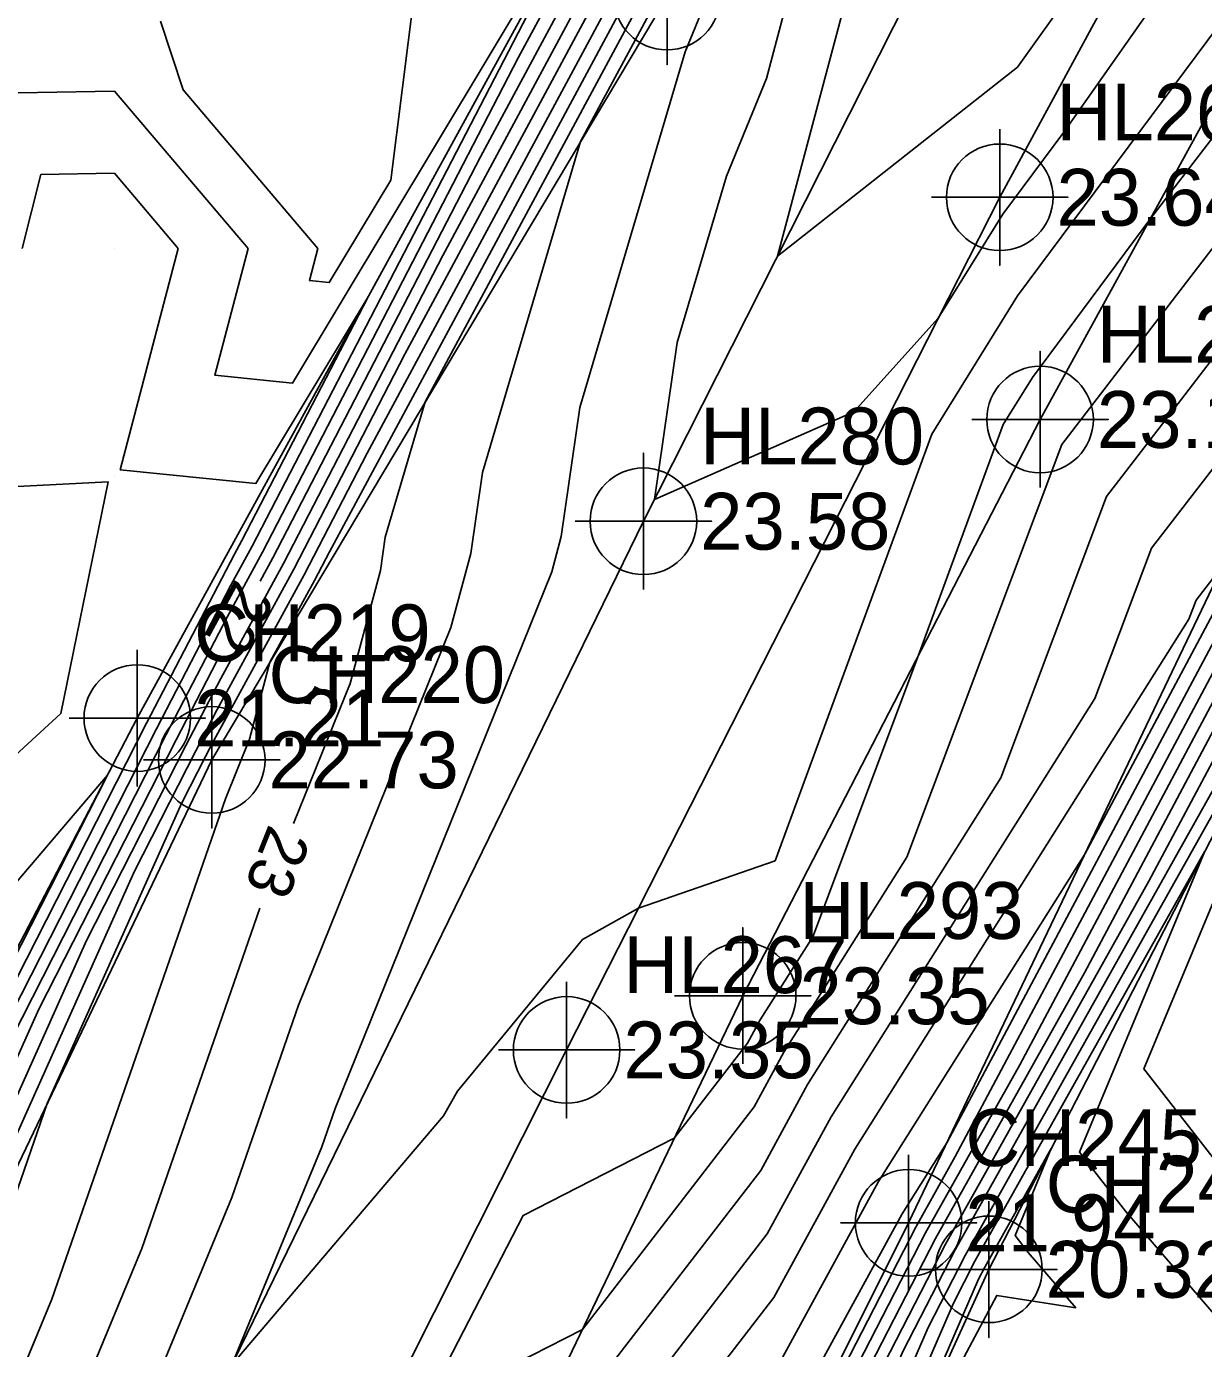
# Model space of a CAD drawing. Extents: x 2531902 to 2533249, y 715219 to 716099.
# Drawn here: x 2532916.1 to 2532967.9, y 715771.6 to 715829.8 of the extents above; entities that cross this region are included whole.
import ezdxf

# ---------------------------------------------------------------- set-up
doc = ezdxf.new("R2010")
doc.units = 0
for name, color, linetype in [('DTM Contours Major', 7, 'Continuous'), ('DTM Contours Major Text', 7, 'Continuous'), ('DTM Contours Minor', 7, 'Continuous'), ('Exist DTM Breakline', 7, 'Continuous'), ('Exist DTM Breakline Cogo Elevation', 7, 'Continuous'), ('Exist DTM Breakline Cogo Number', 7, 'Continuous'), ('Exist DTM Breakline Cogo Point CELL', 7, 'Continuous'), ('Exist DTM Crownline', 7, 'Continuous'), ('Exist DTM Crownline Cogo Elevation', 7, 'Continuous'), ('Exist DTM Crownline Cogo Number', 7, 'Continuous'), ('Exist DTM Crownline Cogo Point CELL', 7, 'Continuous'), ('Exist DTM QL2 LIDAR Elevation Point', 7, 'Continuous'), ('Exist Roads Soil', 7, 'Continuous'), ('Exist Roads Soil Cogo Elevation', 7, 'Continuous'), ('Exist Roads Soil Cogo Number', 7, 'Continuous'), ('Exist Roads Soil Cogo Point CELL', 7, 'Continuous')]:
    doc.layers.add(name, color=color, linetype=linetype)

msp = doc.modelspace()

# ---------------------------------------------------------------- linework, layer by layer
at = {"layer": 'DTM Contours Major'}
for points in [[(2532974.311, 715893.136), (2532962.46, 715871.481), (2532962.278, 715871.136), (2532960.23, 715867.394), (2532948.234, 715846.192), (2532945.525, 715841.222), (2532941.981, 715834.931), (2532940.907, 715832.959), (2532936.106, 715824.028), (2532926.974, 715806.393), (2532926.413, 715805.363)], [(2532972.197, 715883.951), (2532970.304, 715880.392), (2532964.86, 715870.446), (2532963.229, 715867.364), (2532962.476, 715865.987), (2532958.062, 715858.186), (2532947.982, 715839.692), (2532947.015, 715837.976), (2532943.502, 715831.522), (2532933.674, 715813.243), (2532931.908, 715807.29), (2532931.698, 715805.829), (2532930.375, 715800.865), (2532927.885, 715794.695)], [(2532935.185, 715767.309), (2532936.846, 715770.53), (2532940.585, 715772.44), (2532948.143, 715782.24), (2532949.453, 715784.64), (2532954.859, 715793.213), (2532961.679, 715811.367), (2532962.756, 715812.763), (2532974.003, 715827.414), (2532982.304, 715840.432), (2532983.884, 715842.624), (2532986.227, 715846.362), (2532988.704, 715850.418)], [(2532940.427, 715752.913), (2532947.909, 715766.076), (2532949.587, 715768.252), (2532954.651, 715777.527), (2532956.624, 715780.657), (2532968.862, 715803.641), (2532970.137, 715805.875), (2532974.043, 715813.166), (2532980.171, 715824.204), (2532988.171, 715839.431), (2532988.73, 715840.42)], [(2532947.883, 715757.336), (2532952.088, 715765.474), (2532954.69, 715771.469), (2532956.99, 715775.945), (2532968.355, 715796.209), (2532971.516, 715802.146), (2532976.228, 715810.406), (2532976.683, 715811.256), (2532981.302, 715819.574), (2532979.344, 715814.39), (2532979.091, 715812.432), (2532984.65, 715813.744), (2532990.818, 715811.156), (2532984.286, 715810.253), (2532982.785, 715810.371), (2532981.484, 715810.238)], [(2532924.512, 715801.844), (2532922.712, 715798.378), (2532916.679, 715786.53), (2532909.832, 715771.258), (2532907.404, 715766.443), (2532903.158, 715756.872), (2532900.931, 715750.96), (2532890.629, 715729.59), (2532889.617, 715727.08), (2532883.368, 715714.157), (2532882.093, 715711.334)], [(2532926.402, 715790.98), (2532921.205, 715776.01), (2532917.456, 715766.943), (2532915.445, 715761.302), (2532907.4, 715743.928), (2532903.178, 715734.67), (2532899.089, 715725.845), (2532896.932, 715721.119), (2532887.609, 715704.047), (2532886.836, 715702.631), (2532884.884, 715700.293)]]:
    msp.add_lwpolyline(points, dxfattribs=at)
at = {"layer": 'DTM Contours Minor'}
for points in [[(2532978.605, 715897.015), (2532971.537, 715883.729), (2532964.38, 715870.653), (2532963.039, 715868.118), (2532962.027, 715866.268), (2532956.096, 715855.787), (2532947.491, 715839.998), (2532946.008, 715837.367), (2532942.983, 715831.81), (2532929.455, 715806.649), (2532928.803, 715805.39), (2532926.843, 715801.791), (2532925.943, 715798.415), (2532924.885, 715795.792), (2532917.242, 715773.777), (2532914.997, 715768.345), (2532911.892, 715759.638), (2532906.456, 715747.898), (2532899.692, 715733.067), (2532896.805, 715726.836), (2532893.28, 715719.109), (2532886.559, 715706.802)], [(2532979.486, 715896.632), (2532969.071, 715877.054), (2532965.34, 715870.238), (2532963.42, 715866.609), (2532962.925, 715865.706), (2532960.028, 715860.585), (2532948.473, 715839.387), (2532948.022, 715838.585), (2532944.021, 715831.235), (2532940.505, 715824.696), (2532936.189, 715810.144), (2532935.675, 715806.573), (2532934.806, 715803.315), (2532928.105, 715786.707), (2532925.167, 715778.244), (2532919.916, 715765.541), (2532918.998, 715762.966), (2532908.344, 715739.958), (2532906.663, 715736.273), (2532901.372, 715724.854), (2532900.585, 715723.128), (2532888.659, 715701.292)], [(2532980.806, 715896.056), (2532974.415, 715884.041), (2532975.418, 715873.531), (2532973.91, 715870.926), (2532973.877, 715870.057), (2532963.239, 715858.875), (2532955.103, 715841.953), (2532949.17, 715819.66), (2532959.725, 715827.976), (2532969.363, 715841.46), (2532973.494, 715847.335), (2532974.223, 715848.244), (2532975.261, 715849.693), (2532979.719, 715856.686), (2532991.661, 715874.393), (2532992.633, 715875.956), (2532996.105, 715881.12), (2533004.003, 715895.09)], [(2532923.186, 715712.886), (2532930.858, 715737.702), (2532931.519, 715738.867), (2532931.565, 715739.012), (2532935.901, 715749.684), (2532944.529, 715764.866), (2532949.298, 715771.05), (2532953.612, 715778.95), (2532962.696, 715793.355), (2532968.331, 715803.94), (2532968.918, 715804.969), (2532973.515, 715813.549), (2532977.321, 715820.404), (2532987.549, 715839.87), (2532988.835, 715842.147), (2532990.374, 715845.067), (2532998.16, 715859.118), (2533004.671, 715871.406), (2533006.64, 715874.927), (2533008.039, 715877.566), (2533018.511, 715895.173)], [(2532975.237, 715893.742), (2532962.94, 715871.274), (2532962.468, 715870.382), (2532960.68, 715867.113), (2532950.199, 715848.59), (2532946.016, 715840.916), (2532942.988, 715835.54), (2532941.426, 715832.672), (2532934.443, 715819.684), (2532927.431, 715806.142), (2532924.675, 715801.081), (2532923.145, 715798.135), (2532918.776, 715789.555), (2532910.427, 715770.931), (2532908.967, 715768.038), (2532903.853, 715756.506), (2532902.788, 715753.68), (2532891.061, 715729.356), (2532890.683, 715728.417), (2532883.705, 715713.988)], [(2532916.168, 715709.807), (2532922.937, 715719.046), (2532928.431, 715736.817), (2532929.391, 715738.509), (2532929.424, 715738.615), (2532935.705, 715754.076), (2532941.15, 715763.655), (2532949.009, 715773.848), (2532952.572, 715780.372), (2532967.273, 715803.685), (2532967.59, 715804.529), (2532968.767, 715806.054), (2532972.987, 715813.931), (2532974.472, 715816.605), (2532986.926, 715840.31), (2532987.791, 715841.84), (2532989.699, 715845.462), (2532995.142, 715855.284), (2533003.918, 715871.848), (2533005.351, 715874.411), (2533007.293, 715878.074), (2533014.98, 715890.997)], [(2532974.003, 715890.405), (2532963.42, 715871.067), (2532962.658, 715869.627), (2532961.129, 715866.831), (2532952.165, 715850.989), (2532946.508, 715840.61), (2532943.995, 715836.149), (2532941.945, 715832.384), (2532932.78, 715815.339), (2532927.888, 715805.891), (2532924.525, 715799.715), (2532923.578, 715797.892), (2532920.873, 715792.58), (2532911.022, 715770.605), (2532910.531, 715769.633), (2532905.461, 715758.203), (2532904.787, 715756.311), (2532904.568, 715755.838), (2532892.722, 715729.861), (2532892.238, 715728.818), (2532885.975, 715715.09)], [(2532972.77, 715887.067), (2532963.9, 715870.86), (2532962.849, 715868.873), (2532961.578, 715866.55), (2532954.131, 715853.388), (2532946.999, 715840.304), (2532945.001, 715836.758), (2532942.464, 715832.097), (2532931.118, 715810.994), (2532928.346, 715805.641), (2532924.375, 715798.35), (2532924.011, 715797.648), (2532922.97, 715795.605), (2532917.043, 715782.383), (2532913.28, 715771.543), (2532912.537, 715769.747), (2532908.34, 715757.975), (2532905.512, 715751.868), (2532896.207, 715731.464), (2532894.522, 715727.827), (2532889.628, 715717.099)], [(2532910.432, 715708.479), (2532922.688, 715725.206), (2532926.003, 715735.932), (2532927.262, 715738.151), (2532927.284, 715738.218), (2532935.51, 715758.468), (2532937.77, 715762.445), (2532948.721, 715776.645), (2532951.532, 715781.795), (2532963.135, 715800.194), (2532965.619, 715806.809), (2532971.138, 715813.959), (2532972.856, 715816.197), (2532975.967, 715821.075), (2532986.303, 715840.749), (2532986.747, 715841.534), (2532989.025, 715845.857), (2532992.123, 715851.449), (2533003.166, 715872.291), (2533004.063, 715873.895), (2533006.548, 715878.581), (2533011.449, 715886.821)], [(2532913.805, 715732.275), (2532924.716, 715749.822), (2532927.378, 715756.907), (2532927.487, 715757.103), (2532937.989, 715777.463), (2532944.628, 715780.854), (2532947.854, 715785.038), (2532948.414, 715786.062), (2532950.722, 715789.722), (2532955.375, 715802.111), (2532959.105, 715812.252), (2532960.387, 715814.323), (2532965.555, 715821.271), (2532974.576, 715833.023), (2532978.776, 715839.609), (2532982.024, 715844.114), (2532983.417, 715846.335), (2532990.678, 715858.227), (2532998.691, 715872.853), (2532999.363, 715873.971), (2533001.557, 715877.98), (2533006.576, 715886.786)], [(2532952.184, 715840.618), (2532948.685, 715827.47), (2532946.922, 715823.173), (2532944.752, 715815.853), (2532943.758, 715808.958), (2532952.525, 715812.81), (2532956.245, 715816.925), (2532959.082, 715821.509), (2532961.763, 715825.114), (2532974.339, 715842.999)], [(2532909.836, 715712.944), (2532918.233, 715725.627), (2532922.438, 715731.367), (2532923.576, 715735.047), (2532925.134, 715737.794), (2532925.143, 715737.821), (2532931.922, 715754.508), (2532934.359, 715760.993), (2532934.373, 715761.018), (2532935.703, 715763.597), (2532936.543, 715764.026), (2532948.432, 715779.443), (2532950.493, 715783.217), (2532958.997, 715796.704), (2532963.649, 715809.088), (2532966.947, 715813.361), (2532973.429, 715821.806), (2532985.17, 715840.216)], [(2532925.658, 715710.774), (2532927.519, 715718.451), (2532934.964, 715737.049), (2532935.713, 715739.472), (2532935.776, 715739.583), (2532935.847, 715739.806), (2532936.291, 715740.9), (2532940.806, 715748.843), (2532949.984, 715766.604), (2532950.251, 715767.219), (2532955.253, 715776.951), (2532956.992, 715780.051), (2532969.393, 715803.342), (2532971.355, 715806.781), (2532974.571, 715812.784), (2532983.021, 715828.003), (2532988.794, 715838.992)], [(2532913.207, 715826.793), (2532920, 715826.92), (2532925.88, 715820), (2532924.416, 715814.416), (2532927.837, 715814.075), (2532938.492, 715831.82), (2532938.664, 715833.186), (2532935.342, 715836.365), (2532939.783, 715834.071), (2532942.45, 715838.121), (2532939.967, 715833.714), (2532939.869, 715833.533), (2532939.431, 715832.718), (2532926.059, 715806.894), (2532925.125, 715805.179), (2532921.847, 715798.865), (2532912.485, 715780.48)], [(2532948.88, 715837.837), (2532945.112, 715828.649), (2532940.47, 715812.999), (2532939.652, 715807.318), (2532939.238, 715805.765), (2532929.715, 715782.164), (2532929.13, 715780.478), (2532925.165, 715770.887), (2532934.474, 715781.848), (2532935.093, 715782.92), (2532940.599, 715789.593), (2532943.059, 715790.969), (2532949.064, 715793.065), (2532955.964, 715811.824), (2532959.734, 715817.916), (2532974.936, 715838.353)], [(2532929.014, 715712.352), (2532931.932, 715724.385), (2532937.625, 715738.608), (2532937.738, 715738.951), (2532937.807, 715739.124), (2532940.835, 715746.3), (2532951.036, 715766.039), (2532952.47, 715769.344), (2532956.122, 715776.448), (2532962.674, 715788.13), (2532970.455, 715802.744), (2532973.791, 715808.593), (2532975.627, 715812.02), (2532988.72, 715835.602)], [(2532940.388, 715833.246), (2532937.768, 715828.373), (2532926.516, 715806.643), (2532924.975, 715803.813), (2532922.28, 715798.622), (2532914.582, 715783.505)], [(2532926.914, 715709.823), (2532929.726, 715721.418), (2532936.841, 715739.194), (2532936.891, 715739.346), (2532936.977, 715739.56), (2532938.296, 715742.685), (2532950.51, 715766.322), (2532951.361, 715768.281), (2532955.688, 715776.7), (2532959.833, 715784.091), (2532969.924, 715803.043), (2532972.573, 715807.687), (2532975.099, 715812.402), (2532985.871, 715831.803)], [(2532922.029, 715830), (2532923.029, 715826.971), (2532928.952, 715820), (2532928.58, 715818.58), (2532929.45, 715818.493), (2532932.16, 715823.006), (2532933.188, 715831.173)], [(2532915.941, 715820), (2532916.756, 715823.244), (2532920, 715823.304), (2532922.807, 715820), (2532920.253, 715810.253), (2532926.224, 715809.658), (2532931.156, 715817.871), (2532925.602, 715807.145), (2532925.275, 715806.544), (2532921.414, 715799.109), (2532910.388, 715777.455)], [(2532899.773, 715800.227), (2532897.398, 715810), (2532897.261, 715812.739), (2532900, 715819.554), (2532909.037, 715810), (2532910, 715809.229), (2532919.725, 715809.725), (2532917.647, 715799.54), (2532910, 715792.534), (2532901.322, 715798.678), (2532900, 715799.387), (2532899.042, 715799.042), (2532899.667, 715800), (2532899.773, 715800.227)], [(2532933.005, 715714.022), (2532931.949, 715718.326), (2532934.139, 715727.353), (2532938.409, 715738.022), (2532938.585, 715738.557), (2532938.637, 715738.688), (2532943.375, 715749.915), (2532951.562, 715765.757), (2532953.58, 715770.407), (2532956.556, 715776.197), (2532965.514, 715792.17), (2532970.985, 715802.445)], [(2532947.976, 715717.976), (2532942.283, 715720), (2532940.18, 715720.205), (2532940.055, 715721.165), (2532937.82, 715730.273), (2532938.551, 715733.287), (2532939.978, 715736.851), (2532940.278, 715737.768), (2532940.298, 715737.816), (2532948.455, 715757.144), (2532952.614, 715765.192), (2532955.799, 715772.532), (2532957.424, 715775.694), (2532971.196, 715800.249)], [(2532971.835, 715799.607), (2532965.29, 715783.909), (2532968.751, 715779.468)], [(2532909.055, 715784.335), (2532919.697, 715796.83), (2532908.291, 715774.43)], [(2532970.653, 715713.705), (2532960.031, 715720.008), (2532959.955, 715720.065), (2532950.186, 715722.11), (2532942.505, 715722.86), (2532940.762, 715736.22), (2532940.756, 715736.246), (2532940.758, 715736.255), (2532940.762, 715736.265), (2532941.125, 715737.373), (2532941.128, 715737.381), (2532950.995, 715760.759), (2532953.14, 715764.91), (2532956.909, 715773.595), (2532957.859, 715775.442), (2532967.974, 715793.478), (2532962.455, 715780.243), (2532964.478, 715777.648), (2532970, 715771.244)], [(2532962.299, 715773.399), (2532960.204, 715775.828), (2532959.62, 715776.577), (2532961.214, 715780.399), (2532958.293, 715775.191), (2532958.019, 715774.657), (2532953.666, 715764.627), (2532953.535, 715764.373), (2532952.789, 715762.606), (2532953.597, 715763.925), (2532954.78, 715762.105), (2532953.791, 715764.542), (2532953.981, 715764.849), (2532958.814, 715773.943), (2532962.299, 715773.399)]]:
    msp.add_lwpolyline(points, dxfattribs=at)
at = {"layer": 'Exist DTM Breakline'}
for points in [[(2533029.092, 715973.615), (2533002.141, 715931.719), (2532981.109, 715895.925), (2532963.783, 715865.168), (2532944.31, 715831.075), (2532924.281, 715797.496), (2532904.489, 715756.171), (2532883.846, 715713.918), (2532865.559, 715669.748), (2532864.574, 715660.11), (2532866.15, 715657.26), (2532867.929, 715656.562)], [(2533023.854, 715972.817), (2532999.029, 715934.39), (2532976.745, 715897.826), (2532959.919, 715867.589), (2532939.765, 715833.591), (2532921.006, 715799.338), (2532899.767, 715758.656), (2532880.473, 715715.603), (2532864.431, 715683.527), (2532849.717, 715661.422)], [(2532886.275, 715647.711), (2532887.831, 715646.823), (2532890.152, 715647.097), (2532894.459, 715651.173), (2532901.375, 715665.171), (2532911.098, 715687.189), (2532923.196, 715712.636), (2532936.336, 715739.896), (2532954.94, 715777.133), (2532972.649, 715814.175), (2532988.133, 715846.379), (2533005.236, 715879.474), (2533025.701, 715915.803), (2533049.322, 715952.267)], [(2532892.987, 715644.659), (2532898.123, 715649.312), (2532907.034, 715662.801), (2532916.799, 715684.707), (2532927.539, 715709.351), (2532941.275, 715737.303), (2532958.469, 715775.089), (2532977.032, 715811.003), (2532993.183, 715843.422), (2533009.96, 715876.258), (2533030.503, 715912.872), (2533054.575, 715948.316)]]:
    msp.add_lwpolyline(points, dxfattribs=at)
at = {"layer": 'Exist DTM Breakline Cogo Point CELL'}
for points in [[(2532944.31, 715834.075), (2532944.31, 715828.075), (2532944.31, 715831.075), (2532947.31, 715831.075), (2532941.31, 715831.075)], [(2532921.006, 715802.338), (2532921.006, 715796.338), (2532921.006, 715799.338), (2532924.006, 715799.338), (2532918.006, 715799.338)], [(2532924.281, 715800.496), (2532924.281, 715794.496), (2532924.281, 715797.496), (2532927.281, 715797.496), (2532921.281, 715797.496)], [(2532954.94, 715780.133), (2532954.94, 715774.133), (2532954.94, 715777.133), (2532957.94, 715777.133), (2532951.94, 715777.133)], [(2532958.469, 715778.089), (2532958.469, 715772.089), (2532958.469, 715775.089), (2532961.469, 715775.089), (2532955.469, 715775.089)]]:
    msp.add_lwpolyline(points, dxfattribs=at)
for centre in [(2532944.31, 715831.075), (2532921.006, 715799.338), (2532924.281, 715797.496), (2532954.94, 715777.133), (2532958.469, 715775.089)]:
    msp.add_circle(centre, 2.344, dxfattribs=at)
at = {"layer": 'Exist DTM Crownline'}
msp.add_lwpolyline([(2532876.571, 715652.013), (2532884.036, 715667.726), (2532897.268, 715696.346), (2532912.052, 715728.687), (2532925.335, 715755.88), (2532939.894, 715784.74), (2532958.948, 715822.246), (2532974.275, 715850.523), (2532997.485, 715891.381), (2533017.87, 715925.252), (2533038.842, 715957.692)], dxfattribs=at)
at = {"layer": 'Exist DTM Crownline Cogo Point CELL'}
for points in [[(2532958.948, 715825.246), (2532958.948, 715819.246), (2532958.948, 715822.246), (2532961.948, 715822.246), (2532955.948, 715822.246)], [(2532939.894, 715787.74), (2532939.894, 715781.74), (2532939.894, 715784.74), (2532942.894, 715784.74), (2532936.894, 715784.74)]]:
    msp.add_lwpolyline(points, dxfattribs=at)
for centre in [(2532958.948, 715822.246), (2532939.894, 715784.74)]:
    msp.add_circle(centre, 2.344, dxfattribs=at)
at = {"layer": 'Exist DTM QL2 LIDAR Elevation Point'}
for p, q in [((2532920, 715820), (2532920, 715820)), ((2532930, 715820), (2532930, 715820)), ((2532920, 715810), (2532920, 715810))]:
    msp.add_line(p, q, dxfattribs=at)
at = {"layer": 'Exist Roads Soil'}
for points in [[(2533033.002, 715963.552), (2533014.441, 715935.484), (2532992.666, 715901.095), (2532976.471, 715871.314), (2532962.05, 715845.129), (2532943.271, 715807.995), (2532921.982, 715764.363), (2532902.685, 715724.284), (2532889.068, 715694.204), (2532879.255, 715673.169), (2532870.648, 715655.411), (2532876.571, 715652.013), (2532882.435, 715649.375)], [(2532882.435, 715649.375), (2532884.446, 715653.582), (2532893.832, 715673.236), (2532904.082, 715695.07), (2532909.886, 715707.279), (2532923.655, 715737.545), (2532935.371, 715761.586), (2532947.639, 715787.122), (2532960.723, 715812.473), (2532979.299, 715846.297), (2532995.343, 715875.457), (2533008.573, 715897.69), (2533027.701, 715928.616), (2533038.596, 715945.654), (2533044.798, 715955.275)]]:
    msp.add_lwpolyline(points, dxfattribs=at)
at = {"layer": 'Exist Roads Soil Cogo Point CELL'}
for points in [[(2532960.723, 715809.473), (2532960.723, 715815.473), (2532960.723, 715812.473), (2532963.723, 715812.473), (2532957.723, 715812.473)], [(2532943.271, 715804.995), (2532943.271, 715810.995), (2532943.271, 715807.995), (2532946.271, 715807.995), (2532940.271, 715807.995)], [(2532947.639, 715784.122), (2532947.639, 715790.122), (2532947.639, 715787.122), (2532950.639, 715787.122), (2532944.639, 715787.122)]]:
    msp.add_lwpolyline(points, dxfattribs=at)
for centre in [(2532960.723, 715812.473), (2532943.271, 715807.995), (2532947.639, 715787.122)]:
    msp.add_circle(centre, 2.344, dxfattribs=at)

# ---------------------------------------------------------------- texts
at = {"layer": 'DTM Contours Major Text'}
for s, rotation, p in [('22', 241.61935, (2532925.351, 715805.516)), ('23', 248.22824, (2532926.813, 715794.724))]:
    msp.add_text(s, height=2, rotation=rotation, dxfattribs=at).set_placement(p)
at = {"layer": 'Exist DTM Breakline Cogo Elevation'}
for s, p in [('21.21', (2532923.506, 715798.088)), ('22.73', (2532926.781, 715796.246)), ('21.94', (2532957.44, 715775.883)), ('20.32', (2532960.969, 715773.839))]:
    msp.add_text(s, height=2.5, dxfattribs=at).set_placement(p)
at = {"layer": 'Exist DTM Breakline Cogo Number'}
for s, p in [('CH219', (2532923.506, 715801.838)), ('CH220', (2532926.781, 715799.996)), ('CH245', (2532957.44, 715779.633)), ('CH246', (2532960.969, 715777.589))]:
    msp.add_text(s, height=2.5, dxfattribs=at).set_placement(p)
at = {"layer": 'Exist DTM Crownline Cogo Elevation'}
for s, p in [('23.64', (2532961.448, 715820.996)), ('23.35', (2532942.394, 715783.49))]:
    msp.add_text(s, height=2.5, dxfattribs=at).set_placement(p)
at = {"layer": 'Exist DTM Crownline Cogo Number'}
for s, p in [('HL268', (2532961.448, 715824.746)), ('HL267', (2532942.394, 715787.24))]:
    msp.add_text(s, height=2.5, dxfattribs=at).set_placement(p)
at = {"layer": 'Exist Roads Soil Cogo Elevation'}
for s, p in [('23.10', (2532963.223, 715811.223)), ('23.58', (2532945.771, 715806.745)), ('23.35', (2532950.139, 715785.872))]:
    msp.add_text(s, height=2.5, dxfattribs=at).set_placement(p)
at = {"layer": 'Exist Roads Soil Cogo Number'}
for s, p in [('HL294', (2532963.223, 715814.973)), ('HL280', (2532945.771, 715810.495)), ('HL293', (2532950.139, 715789.622))]:
    msp.add_text(s, height=2.5, dxfattribs=at).set_placement(p)

doc.saveas('drawing.dxf')
